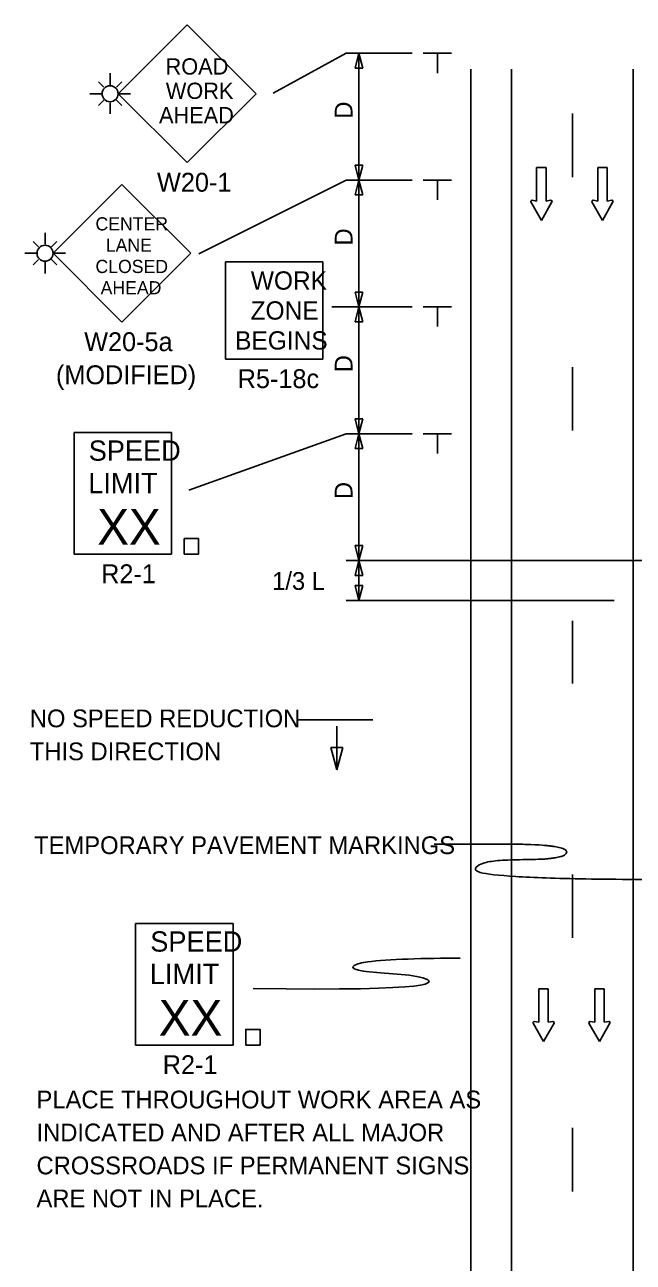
# Model space of a CAD drawing. Extents: x 16577 to 18475, y 5712 to 6919.
# Drawn here: x 16730.9 to 16970.7, y 6431 to 6919 of the extents above; entities that cross this region are included whole.
import ezdxf

# ---------------------------------------------------------------- set-up
doc = ezdxf.new("R2010")
doc.units = 0
for name, color, linetype in [('ALI_LEGAL_EX', 7, 'Continuous'), ('MT_SCRATCH_LEVEL_E', 7, 'Continuous'), ('PAVT_EDGE_EX', 7, 'Continuous'), ('TRAFFIC_SIGNS_PR', 7, 'Continuous'), ('TYPICAL_TEXT_DIMEN_PR', 7, 'Continuous')]:
    doc.layers.add(name, color=color, linetype=linetype)

msp = doc.modelspace()

# ---------------------------------------------------------------- linework, layer by layer
at = {"layer": 'ALI_LEGAL_EX'}
for points in [[(16946.75, 6883.94), (16946.75, 6858.94)], [(16946.75, 6783.94), (16946.75, 6758.94)], [(16946.75, 6683.94), (16946.75, 6659.28)], [(16946.75, 6583.94), (16946.75, 6558.94)], [(16946.75, 6483.94), (16946.75, 6458.94)]]:
    msp.add_lwpolyline(points, dxfattribs=at)
at = {"layer": 'MT_SCRATCH_LEVEL_E'}
for p, q in [((16936.42, 6862.73), (16932.68, 6862.73)), ((16932.68, 6862.73), (16932.68, 6849.48)), ((16936.42, 6862.73), (16932.68, 6862.73)), ((16932.68, 6862.73), (16932.68, 6849.48)), ((16936.42, 6849.48), (16936.42, 6862.73)), ((16936.42, 6849.48), (16936.42, 6862.73)), ((16960.49, 6862.73), (16956.75, 6862.73)), ((16956.75, 6862.73), (16956.75, 6849.48)), ((16960.49, 6862.73), (16956.75, 6862.73)), ((16956.75, 6862.73), (16956.75, 6849.48)), ((16960.49, 6849.48), (16960.49, 6862.73)), ((16960.49, 6849.48), (16960.49, 6862.73)), ((16930.42, 6849.11), (16934.57, 6841.87)), ((16930.42, 6849.11), (16934.57, 6841.87)), ((16932.68, 6849.48), (16930.9, 6849.79)), ((16932.68, 6849.48), (16930.9, 6849.79)), ((16934.57, 6841.87), (16938.68, 6849.11)), ((16934.57, 6841.87), (16938.68, 6849.11)), ((16938.2, 6849.79), (16936.42, 6849.48)), ((16938.2, 6849.79), (16936.42, 6849.48)), ((16954.49, 6849.11), (16958.64, 6841.87)), ((16954.49, 6849.11), (16958.64, 6841.87)), ((16956.75, 6849.48), (16954.97, 6849.79)), ((16956.75, 6849.48), (16954.97, 6849.79)), ((16958.64, 6841.87), (16962.75, 6849.11)), ((16958.64, 6841.87), (16962.75, 6849.11)), ((16962.27, 6849.79), (16960.49, 6849.48)), ((16962.27, 6849.79), (16960.49, 6849.48)), ((16933.54, 6525.61), (16933.54, 6538.86)), ((16933.54, 6538.86), (16937.28, 6538.86)), ((16933.54, 6525.61), (16933.54, 6538.86)), ((16933.54, 6538.86), (16937.28, 6538.86)), ((16937.28, 6538.86), (16937.28, 6525.61)), ((16937.28, 6538.86), (16937.28, 6525.61)), ((16955.57, 6525.61), (16955.57, 6538.86)), ((16955.57, 6538.86), (16959.31, 6538.86)), ((16955.57, 6525.61), (16955.57, 6538.86)), ((16955.57, 6538.86), (16959.31, 6538.86)), ((16959.31, 6538.86), (16959.31, 6525.61)), ((16959.31, 6538.86), (16959.31, 6525.61)), ((16935.39, 6517.99), (16931.28, 6525.24)), ((16935.39, 6517.99), (16931.28, 6525.24)), ((16931.76, 6525.92), (16933.54, 6525.61)), ((16931.76, 6525.92), (16933.54, 6525.61)), ((16939.54, 6525.24), (16935.39, 6517.99)), ((16939.54, 6525.24), (16935.39, 6517.99)), ((16937.28, 6525.61), (16939.06, 6525.92)), ((16937.28, 6525.61), (16939.06, 6525.92)), ((16957.42, 6517.99), (16953.31, 6525.24)), ((16957.42, 6517.99), (16953.31, 6525.24)), ((16953.8, 6525.92), (16955.57, 6525.61)), ((16953.8, 6525.92), (16955.57, 6525.61)), ((16961.57, 6525.24), (16957.42, 6517.99)), ((16961.57, 6525.24), (16957.42, 6517.99)), ((16959.31, 6525.61), (16961.09, 6525.92)), ((16959.31, 6525.61), (16961.09, 6525.92))]:
    msp.add_line(p, q, dxfattribs=at)
for centre, start, end in [((16930.83, 6849.33), 80.0362, 209.7731), ((16930.83, 6849.33), 80.0362, 209.7731), ((16938.27, 6849.33), 330.4248, 99.9638), ((16938.27, 6849.33), 330.4248, 99.9638), ((16954.9, 6849.33), 80.0362, 209.7731), ((16954.9, 6849.33), 80.0362, 209.7731), ((16962.34, 6849.33), 330.4248, 99.9638), ((16962.34, 6849.33), 330.4248, 99.9638), ((16931.69, 6525.46), 80.0362, 209.5752), ((16931.69, 6525.46), 80.0362, 209.5752), ((16939.13, 6525.46), 330.2269, 99.9638), ((16939.13, 6525.46), 330.2269, 99.9638), ((16953.72, 6525.46), 80.0362, 209.5752), ((16953.72, 6525.46), 80.0362, 209.5752), ((16961.16, 6525.46), 330.2269, 99.9638), ((16961.16, 6525.46), 330.2269, 99.9638)]:
    msp.add_arc(centre, 0.463, start, end, dxfattribs=at)
at = {"layer": 'PAVT_EDGE_EX'}
for p, q in [((16906.75, 6901.43), (16906.75, 6139.45)), ((16922.75, 6901.43), (16922.75, 6139.45)), ((16970.75, 6901.43), (16970.75, 6139.45))]:
    msp.add_line(p, q, dxfattribs=at)
at = {"layer": 'TRAFFIC_SIGNS_PR'}
for p, q in [((16794.87, 6919), (16767.69, 6891.81)), ((16822.06, 6891.81), (16794.87, 6919)), ((16762.02, 6894.33), (16759.91, 6896.44)), ((16764.53, 6895.37), (16764.53, 6899.87)), ((16767.04, 6894.33), (16769.15, 6896.44)), ((16761.38, 6891.81), (16756.54, 6891.81)), ((16767.69, 6891.81), (16794.87, 6864.63)), ((16767.69, 6891.81), (16772.57, 6891.81)), ((16794.87, 6864.63), (16822.06, 6891.81)), ((16762.02, 6889.3), (16759.91, 6887.19)), ((16764.53, 6883.85), (16764.53, 6888.26)), ((16767.04, 6889.3), (16769.15, 6887.19)), ((16769.2, 6856.04), (16742.05, 6828.88)), ((16796.35, 6828.88), (16769.2, 6856.04)), ((16736.38, 6831.4), (16734.27, 6833.51)), ((16738.9, 6832.44), (16738.9, 6836.94)), ((16741.41, 6831.4), (16743.52, 6833.51)), ((16735.74, 6828.88), (16730.9, 6828.88)), ((16742.05, 6828.88), (16746.93, 6828.88)), ((16742.05, 6828.88), (16769.2, 6801.73)), ((16769.2, 6801.73), (16796.35, 6828.88)), ((16736.38, 6826.37), (16734.27, 6824.26)), ((16738.9, 6820.92), (16738.9, 6825.33)), ((16741.41, 6826.37), (16743.52, 6824.26)), ((16810.02, 6787.16), (16810.02, 6825.56)), ((16810.02, 6825.56), (16848.42, 6825.56)), ((16848.42, 6787.16), (16848.42, 6825.56)), ((16810.02, 6787.16), (16848.42, 6787.16)), ((16750.34, 6758.21), (16788.74, 6758.21)), ((16750.34, 6710.21), (16750.34, 6758.21)), ((16788.74, 6710.21), (16788.74, 6758.21)), ((16750.34, 6710.21), (16788.74, 6710.21)), ((16774.62, 6564.62), (16813.02, 6564.62)), ((16774.62, 6516.62), (16774.62, 6564.62)), ((16813.02, 6516.62), (16813.02, 6564.62)), ((16774.62, 6516.62), (16813.02, 6516.62))]:
    msp.add_line(p, q, dxfattribs=at)
for points in [[(16793.76, 6710.21), (16799.35, 6710.21), (16799.35, 6716.38), (16793.76, 6716.38)], [(16818.04, 6516.62), (16823.63, 6516.62), (16823.63, 6522.79), (16818.04, 6522.79)]]:
    msp.add_lwpolyline(points, close=True, dxfattribs=at)
for centre in [(16764.53, 6891.81), (16738.89, 6828.88)]:
    msp.add_circle(centre, 3.15, dxfattribs=at)
at = {"layer": 'TYPICAL_TEXT_DIMEN_PR'}
for p, q in [((16857.65, 6907.73), (16828.81, 6891.99)), ((16857.65, 6907.73), (16883.65, 6907.73)), ((16861.08, 6901.87), (16862.65, 6907.73)), ((16862.65, 6907.73), (16864.22, 6901.87)), ((16862.65, 6857.73), (16862.65, 6907.73)), ((16887.9, 6907.73), (16899.15, 6907.73)), ((16893.53, 6907.73), (16893.53, 6899.95)), ((16862.65, 6901.87), (16861.08, 6901.87)), ((16864.22, 6901.87), (16862.65, 6901.87)), ((16862.65, 6857.73), (16861.08, 6863.6)), ((16861.08, 6863.6), (16862.65, 6863.6)), ((16862.65, 6863.6), (16864.22, 6863.6)), ((16864.22, 6863.6), (16862.65, 6857.73)), ((16857.65, 6857.73), (16799.5, 6828.69)), ((16857.65, 6857.73), (16883.65, 6857.73)), ((16861.08, 6851.87), (16862.65, 6857.73)), ((16862.65, 6857.73), (16864.22, 6851.87)), ((16862.65, 6807.73), (16862.65, 6857.73)), ((16887.9, 6857.73), (16899.15, 6857.73)), ((16893.53, 6857.73), (16893.53, 6849.95)), ((16862.65, 6851.87), (16861.08, 6851.87)), ((16864.22, 6851.87), (16862.65, 6851.87)), ((16862.65, 6807.73), (16861.08, 6813.6)), ((16861.08, 6813.6), (16862.65, 6813.6)), ((16862.65, 6813.6), (16864.22, 6813.6)), ((16864.22, 6813.6), (16862.65, 6807.73)), ((16851.93, 6807.73), (16883.65, 6807.73)), ((16861.08, 6801.87), (16862.65, 6807.73)), ((16862.65, 6807.73), (16864.22, 6801.87)), ((16862.65, 6757.73), (16862.65, 6807.73)), ((16887.9, 6807.73), (16899.15, 6807.73)), ((16893.53, 6807.73), (16893.53, 6799.95)), ((16862.65, 6801.87), (16861.08, 6801.87)), ((16864.22, 6801.87), (16862.65, 6801.87)), ((16862.65, 6757.73), (16861.08, 6763.6)), ((16861.08, 6763.6), (16862.65, 6763.6)), ((16862.65, 6763.6), (16864.22, 6763.6)), ((16864.22, 6763.6), (16862.65, 6757.73)), ((16857.65, 6757.73), (16795.55, 6735.45)), ((16857.65, 6757.73), (16883.65, 6757.73)), ((16861.08, 6751.87), (16862.65, 6757.73)), ((16862.65, 6707.73), (16862.65, 6757.73)), ((16862.65, 6757.73), (16864.22, 6751.87)), ((16887.9, 6757.73), (16899.15, 6757.73)), ((16893.53, 6757.73), (16893.53, 6749.95)), ((16862.65, 6751.87), (16861.08, 6751.87)), ((16864.22, 6751.87), (16862.65, 6751.87)), ((16862.65, 6707.73), (16861.08, 6713.6)), ((16861.08, 6713.6), (16862.65, 6713.6)), ((16862.65, 6713.6), (16864.22, 6713.6)), ((16864.22, 6713.6), (16862.65, 6707.73)), ((16987.84, 6707.73), (16857.65, 6707.73)), ((16861.08, 6701.87), (16862.65, 6707.73)), ((16862.65, 6691.97), (16862.65, 6707.73)), ((16862.65, 6707.73), (16864.22, 6701.87)), ((16862.65, 6701.87), (16861.08, 6701.87)), ((16864.22, 6701.87), (16862.65, 6701.87)), ((16862.65, 6691.97), (16861.08, 6697.83)), ((16861.08, 6697.83), (16862.65, 6697.83)), ((16862.65, 6697.83), (16864.22, 6697.83)), ((16864.22, 6697.83), (16862.65, 6691.97)), ((16857.65, 6691.98), (16963.28, 6691.98)), ((16868.06, 6644.84), (16838.62, 6644.84)), ((16853.88, 6642.34), (16853.88, 6625.21)), ((16853.88, 6634.01), (16851.53, 6634.01)), ((16851.53, 6634.01), (16853.88, 6625.21)), ((16853.88, 6625.21), (16856.24, 6634.01)), ((16856.24, 6634.01), (16853.88, 6634.01))]:
    msp.add_line(p, q, dxfattribs=at)
for points, degree in [([(16993.34, 6581.84), (16908.56, 6581.84), (16908.56, 6589.72), (16944.52, 6589.72), (16944.52, 6595.87), (16896.23, 6595.87), (16892.29, 6595.87)], 2), ([(16821, 6538.99), (16894.49, 6537.77), (16893.35, 6544.88), (16858.59, 6544.88), (16858.59, 6550.17), (16888.78, 6550.85), (16902.57, 6550.96)], 3)]:
    msp.add_open_spline(points, degree=degree, dxfattribs=at)

# ---------------------------------------------------------------- texts
at = {"layer": 'TRAFFIC_SIGNS_PR'}
for s, height, p in [('ROAD', 6.408, (16786.4, 6899.36)), ('WORK', 6.408, (16786.51, 6889.75)), ('AHEAD', 6.408, (16783.82, 6880.14)), ('W20-1', 7.449, (16783.03, 6853.17)), ('CENTER', 5.2, (16758.78, 6837.89)), ('LANE', 5.2, (16762.85, 6829.49)), ('CLOSED', 5.2, (16758.78, 6821.09)), ('AHEAD', 5.2, (16760.81, 6812.69)), ('WORK', 7.217, (16820.02, 6814.53)), ('ZONE', 7.217, (16819.91, 6802.72)), ('BEGINS', 7.217, (16813.83, 6790.91)), ('W20-5a', 7.44, (16754.34, 6790.29)), ('(MODIFIED)', 7.44, (16743.2, 6777.25)), ('R5-18c', 7.44, (16814.84, 6775.72)), ('SPEED', 8, (16756.11, 6747.07)), ('LIMIT', 8, (16755.95, 6734.27)), ('XX', 14.031, (16759.46, 6713.97)), ('R2-1', 7.44, (16761.02, 6698.77)), ('SPEED', 8, (16780.39, 6553.48)), ('LIMIT', 8, (16780.23, 6540.68)), ('XX', 14.031, (16783.73, 6520.38)), ('R2-1', 7.44, (16785.3, 6505.18)), ('PLACE THROUGHOUT WORK AREA AS', 7, (16735.54, 6491.66)), ('INDICATED AND AFTER ALL MAJOR', 7, (16735.54, 6478.66)), ('CROSSROADS IF PERMANENT SIGNS', 7, (16735.54, 6465.66)), ('ARE NOT IN PLACE.', 7, (16735.54, 6452.66))]:
    msp.add_text(s, height=height, dxfattribs=at).set_placement(p)
at = {"layer": 'TYPICAL_TEXT_DIMEN_PR'}
for p in [(16860.09, 6881.95), (16860.09, 6831.95), (16860.09, 6781.95), (16860.09, 6731.95)]:
    msp.add_text('D', height=7, rotation=90, dxfattribs=at).set_placement(p)
for s, p in [('1/3 L', (16828.41, 6696.15)), ('NO SPEED REDUCTION', (16732.9, 6641.96)), ('THIS DIRECTION', (16732.9, 6628.96)), ('TEMPORARY PAVEMENT MARKINGS', (16734.6, 6591.95))]:
    msp.add_text(s, height=7, dxfattribs=at).set_placement(p)

doc.saveas('drawing.dxf')
